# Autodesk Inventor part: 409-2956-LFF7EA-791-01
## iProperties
Shininess: 64.0
Angle Display Precision: 2
Document Length Units: 11272
Document Angle Units: 11279
Document Time Units: 11290
Document Mass Units: 11286
Document Length Units Precision: 3
Document Angle Units Precision: 2
Compacted: True
Created: 2002-04
Part Number: 409-2956-LFF7EA-791-01
Description: DISCHARGE PIPE STAND ANGLE
Document SubType Name: Modeling
Designer: S. Boerckel
Mass: 4144.19 g
Surface Area: 1729.53 cm^2
Volume: 527.922 cm^3
Density: 7.85 g/cm^3
Cost Center: 2 x 2 x 1/4 ANGLE
Material: ASTM A36
Engineer: S. Boerckel
User Status: SAW
Density: 0.0
Volumn: 0.0
Area: 0.0
PropertySet Name: Model Information
Control State: 0
Master: False
Checked Out: False
length: 34.440 in
SMR: =<COST CENTER> - <MATERIAL>
Author: S. Boerckel
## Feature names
1. Extrusion1
